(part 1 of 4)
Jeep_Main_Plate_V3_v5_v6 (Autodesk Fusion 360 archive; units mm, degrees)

design "Jeep_Main_Plate_V3_v5" references "Jeep_Left_Side_v8", "Jeep_Right_Side_v2"
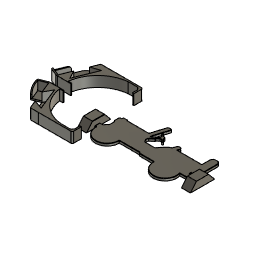
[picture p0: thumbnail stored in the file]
sketch "Sketch1" plane through (0, 0, 0) normal (0, 0, 1) x axis (1, 0, 0)
  line L1 (210, -40) -> (50, -40)
  line L2 (210, -120) -> (210, -40)
  line L3 (50, -120) -> (210, -120)
  line L4 (50, -40) -> (50, -120)
  point P2 (50, -40)
  point P3 (210, -40)
  point P5 (50, -120)
  horizontal L1
  vertical L2
  horizontal L3
  vertical L4
  dimension "d1" distance P2 P3 = 160
  dimension "d2" distance P2 P5 = 80
extrude "Extrude1" new body sketch "Sketch1" along normal blind 10.382
sketch "Sketch2" plane through (0, 0, 10.382) normal (0, 0, 1) x axis (-1, 0, 0)
  line L1 (-210, 120) -> (-50, 120)
  line L2 (-210, 40) -> (-210, 120)
  line L3 (-50, 40) -> (-210, 40)
  line L4 (-50, 120) -> (-50, 40)
  line L5 (-210, 120) -> (-50, 120)
  line L6 (-210, 118) -> (-210, 120)
  line L7 (-50, 118) -> (-210, 118)
  line L8 (-50, 120) -> (-50, 118)
  point P2 (-50, 120)
  point P6 (-50, 120)
  point P9 (-50, 118)
  horizontal L5
  vertical L6
  horizontal L7
  vertical L8
  coincident P2 P6
  dimension "d5" distance P6 P9 = 2
extrude "Extrude2" add sketch "Sketch2" profile of L1 L2 L4 L5 L6 L7 L8 along normal blind 11.697
sketch "Sketch3" plane through (50, 0, 0) normal (-1, 0, 0) x axis (0, -1, 0)
  line L1 (120, 0) -> (40, 0)
  line L2 (120, 22.079) -> (120, 0)
  line L3 (118, 22.079) -> (120, 22.079)
  line L4 (118, 10.382) -> (118, 22.079)
  line L5 (40, 10.382) -> (118, 10.382)
  line L6 (40, 0) -> (40, 10.382)
  line L7 (100.521, 10.382) -> (118, 10.382)
  line L8 (118, 0) -> (118, 10.382)
  line L9 (109.201, 0) -> (118, 0)
  line L10 (74.448, 0) -> (109.201, 0)
  line L11 (83.183, 10.382) -> (100.521, 10.382)
  line L12 (74.448, 0) -> (83.183, 10.382)
  line L13 (109.201, 0) -> (100.521, 10.382)
  point P6 (118, 10.382)
  point P8 (118, 10.382)
  point P10 (118, 0)
  point P9 (100.521, 10.382)
  point P11 (109.201, 0)
  point P12 (74.448, 0)
  point P13 (83.183, 10.382)
  coincident P6 P8
  coincident L1 P10
  dimension "d8" distance P8 P9 = 17.479
  dimension "d9" distance P10 P11 = 8.799
  dimension "d10" distance P11 P12 = 34.753
  dimension "d11" distance P9 P13 = 17.338
extrude "Extrude3" cut sketch "Sketch3" profile of L1 L2 L3 L4 L5 L6 L7 L8 L9 L12 L13 against normal blind 13
sketch "Sketch4" plane through (0, 0, 10.382) normal (0, 0, 1) x axis (-1, 0, 0)
  line L1 (-63, 83.183) -> (-63, 40)
  line L2 (-50, 83.183) -> (-63, 83.183)
  line L3 (-50, 100.521) -> (-50, 83.183)
  line L4 (-63, 100.521) -> (-50, 100.521)
  line L5 (-63, 118) -> (-63, 100.521)
  line L6 (-210, 118) -> (-63, 118)
  line L7 (-210, 40) -> (-210, 118)
  line L8 (-63, 40) -> (-210, 40)
  line L9 (-63, 66.387) -> (-63, 74.448)
  line L10 (-130, 91.852) -> (-50, 91.852)
  line L11 (-63, 120) -> (-210, 120)
  line L12 (-130, 80) -> (-130, 120)
  line L13 (-78.4111, 82) -> (-181.5889, 82)
  line L14 (-78.4111, 78) -> (-78.4111, 82)
  line L15 (-181.5889, 78) -> (-78.4111, 78)
  line L16 (-181.5889, 82) -> (-181.5889, 78)
  line L17 (-78.4111, 78) -> (-181.5889, 82)
  line L18 (-181.5889, 78) -> (-78.4111, 82)
  line L19 (-181.5889, 78.2155) -> (-176.0304, 78.2155)
  line L20 (-181.5889, 82) -> (-181.5889, 78.2155)
  line L21 (-176.0304, 82) -> (-181.5889, 82)
  line L22 (-176.0304, 78.2155) -> (-176.0304, 82)
  circle C1 centre (-130, 80) radius 33.45
  point P11 (-63, 74.448)
  point P12 (-63, 74.448)
  point P14 (-50, 91.852)
  point P18 (-130, 120)
  point P19 (-130, 80)
  point P20 (-130, 80)
  point P25 (-130, 80)
  point P26 (-176.0304, 78.2155)
  point P13 (-63, 66.387)
  point P15 (-130, 91.852)
  point P22 (-78.4111, 82)
  point P23 (-78.4111, 78)
  coincident P11 P12
  midpoint L3 P14
  coincident L11 P18
  coincident P19 P20
  perpendicular L13 L14
  parallel L13 L15
  parallel L14 L16
  horizontal L13
  coincident L17 P25
  coincident L18 P25
  coincident P20 P25
  horizontal L19
  vertical L20
  horizontal L21
  vertical L22
  coincident L18 P26
  dimension "d14" distance P12 P13 = 8.061
  dimension "d15" distance P14 P15 = 80
  dimension "d16" distance P18 P19 = 40
  dimension "d17" diameter C1 = 66.9
  dimension "d20" distance P22 P23 = 4
extrude "Extrude6" cut sketch "Sketch4" profile of L13 L16 L19 L20 L21 L22 against normal blind 19
extrude "Extrude5" cut sketch "Sketch4" profile of L10 L12 C1 L13 L15 L16 against normal blind 8
extrude "Extrude4" cut sketch "Sketch4" profile of L10 L12 C1 against normal blind 7.7
sketch "Sketch5" plane through (210, 0, 0) normal (1, 0, 0) x axis (0, 1, 0)
  line L1 (-40, 0) -> (-120, 0)
  line L2 (-40, 10.382) -> (-40, 0)
  line L3 (-118, 10.382) -> (-40, 10.382)
  line L4 (-118, 22.079) -> (-118, 10.382)
  line L5 (-120, 22.079) -> (-118, 22.079)
  line L6 (-120, 10.382) -> (-120, 22.079)
  line L7 (-120, 0) -> (-120, 10.382)
  line L8 (-100.521, 10.382) -> (-109.201, 0)
  line L9 (-74.448, 0) -> (-83.183, 10.382)
  point P9 (-109.201, 0)
  point P11 (-109.201, 0)
  point P10 (-100.521, 10.382)
  point P12 (-100.521, 10.382)
  point P13 (-83.183, 10.382)
  point P15 (-83.183, 10.382)
  point P14 (-74.448, 0)
  point P16 (-74.448, 0)
  coincident P9 P11
  coincident P10 P12
  coincident P13 P15
  coincident P14 P16
extrude "Extrude7" cut sketch "Sketch5" against normal blind 13
sketch "Sketch6" plane through (0, 0, 10.382) normal (0, 0, 1) x axis (-1, 0, 0)
  line L1 (-197, 100.521) -> (-197, 118)
  line L2 (-210, 100.521) -> (-197, 100.521)
  line L3 (-210, 83.183) -> (-210, 100.521)
  line L4 (-197, 83.183) -> (-210, 83.183)
  line L5 (-197, 40) -> (-197, 83.183)
  line L6 (-63, 40) -> (-197, 40)
  line L7 (-63, 83.183) -> (-63, 40)
  line L8 (-50, 83.183) -> (-63, 83.183)
  line L9 (-50, 100.521) -> (-50, 83.183)
  line L10 (-63, 100.521) -> (-50, 100.521)
  line L11 (-63, 118) -> (-63, 100.521)
  line L12 (-197, 118) -> (-63, 118)
  line L13 (-181.5889, 78) -> (-163.3902, 78)
  line L14 (-181.5889, 82) -> (-181.5889, 78)
  line L15 (-163.3902, 82) -> (-181.5889, 82)
  line L16 (-63, 66.387) -> (-63, 74.448)
  line L17 (-197, 66.387) -> (-197, 74.448)
  arc A1 centre (-56.3945, 2.5515) radius 64.1763 clockwise from (-108.5118, 40) to (-63, 66.387)
  arc A2 centre (-337.6055, 2.5515) radius 64.1763 clockwise from (-331, 66.387) to (-285.4882, 40)
  arc A3 centre (-203.6081, 2.6588) radius 64.1763 clockwise from (-197.0026, 66.4943) to (-151.4908, 40.1073)
  arc A4 centre (-203.6081, 2.6588) radius 64.1763 clockwise from (-197.0026, 66.4943) to (-151.4908, 40.1073)
  arc A5 centre (-130, 80) radius 33.45 clockwise from (-163.3902, 82) to (-163.3902, 78)
  point P18 (-63, 74.448)
  point P19 (-63, 74.448)
  point P21 (-108.5118, 40)
  point P23 (-197, 74.448)
  point P24 (-197, 74.448)
  point P20 (-63, 66.387)
  point P27 (-331, 66.387)
  point P28 (-285.4882, 40)
  point P25 (-197, 66.387)
  coincident P18 P19
  coincident L6 P21
  coincident P23 P24
  symmetric L5 P20 P27
  symmetric L5 P21 P28
  symmetric L5 A1 A2
  dimension "d28" distance P19 P20 = 8.061
  dimension "d29" distance P24 P25 = 8.061
fillet "Fillet2" radius 50
fillet "Fillet3" radius 50
sketch "Sketch7" plane through (0, 0, 22.079) normal (0, 0, 1) x axis (-1, 0, 0)
  line L1 (-197, 118) -> (-197, 120)
  line L2 (-63, 118) -> (-197, 118)
  line L3 (-63, 120) -> (-63, 118)
  line L4 (-197, 120) -> (-63, 120)
  line L5 (-50, 100.521) -> (-50, 109.201)
  line L6 (-50, 74.448) -> (-50, 109.201)
  line L7 (-50, 109.201) -> (-63, 109.201)
  line L8 (-50, 124) -> (-50, 107.6507)
  line L9 (-71, 120) -> (-50, 120)
  line L10 (-106, 120) -> (-71, 120)
  line L11 (-71, 120) -> (-106, 120)
  line L12 (-71, 118) -> (-71, 120)
  line L13 (-106, 118) -> (-71, 118)
  line L14 (-106, 120) -> (-106, 118)
  point P10 (-50, 107.6507)
  point P12 (-50, 120)
  point P16 (-71, 118)
  point P13 (-71, 120)
  point P14 (-106, 120)
  coincident L5 P10
  perpendicular L7 L8
  coincident L8 P12
  horizontal L11
  vertical L12
  horizontal L13
  vertical L14
  coincident L2 P16
  dimension "d32" distance P12 P13 = 21
  dimension "d33" distance P13 P14 = 35
extrude "Extrude8" cut sketch "Sketch7" profile of L2 L4 L10 L11 L12 L13 L14 against normal blind 12
fillet "Fillet4" radius 2
fillet "Fillet5" radius 2
sketch "Sketch8" plane through (0, 0, 10.382) normal (0, 0, 1) x axis (-1, 0, 0)
  line L1 (-181.5889, 78) -> (-163.3902, 78)
  line L2 (-181.5889, 82) -> (-181.5889, 78)
  line L3 (-163.3902, 82) -> (-181.5889, 82)
  curve K1 (-197, 83.183) -> (-147.2728, 40)
  line L4 (-112.7272, 40) -> (-147.2728, 40)
  curve K2 (-112.7272, 40) -> (-63, 83.183)
  line L5 (-50, 83.183) -> (-63, 83.183)
  line L6 (-50, 100.521) -> (-50, 83.183)
  line L7 (-63, 100.521) -> (-50, 100.521)
  line L8 (-63, 118) -> (-63, 100.521)
  line L9 (-71, 118) -> (-63, 118)
  line L10 (-106, 118) -> (-71, 118)
  line L11 (-197, 118) -> (-106, 118)
  line L12 (-197, 100.521) -> (-197, 118)
  line L13 (-210, 100.521) -> (-197, 100.521)
  line L14 (-210, 83.183) -> (-210, 100.521)
  line L15 (-197, 83.183) -> (-210, 83.183)
  arc A1 centre (-130, 80) radius 33.45 clockwise from (-163.3902, 82) to (-163.3902, 78)
extrude "Extrude9" add of existing geometry blind 0.3
extrude "Extrude10" add of existing geometry blind 0.003
sketch "Sketch9" plane through (0, -120, 0) normal (0, -1, 0) x axis (1, 0, 0)
  line L1 (106, 10.382) -> (106, 20.079)
  line L2 (71, 10.382) -> (106, 10.382)
  line L3 (71, 20.079) -> (71, 10.382)
  line L4 (63, 22.079) -> (69, 22.079)
  line L5 (63, 0) -> (63, 22.079)
  line L6 (197, 0) -> (63, 0)
  line L7 (197, 22.079) -> (197, 0)
  line L8 (108, 22.079) -> (197, 22.079)
  line L9 (189, 10.382) -> (197, 10.382)
  line L10 (189, 22.079) -> (189, 10.382)
  line L11 (106, 10.382) -> (189, 10.382)
  arc A1 centre (108, 20.079) radius 2 clockwise from (106, 20.079) to (108, 22.079)
  arc A2 centre (69, 20.079) radius 2 clockwise from (69, 22.079) to (71, 20.079)
  point P14 (197, 10.382)
  point P15 (197, 10.382)
  point P17 (189, 22.079)
  point P5 (106, 10.382)
  point P18 (106, 10.382)
  point P16 (189, 10.382)
  coincident P14 P15
  coincident L8 P17
  vertical L10
  coincident P5 P18
  perpendicular L1 L11
  dimension "d42" distance P15 P16 = 8
extrude "Extrude11" cut sketch "Sketch9" profile of A1 L1 L8 L10 L11 against normal blind 8
sketch "Sketch10" plane through (0, 0, 10.382) normal (0, 0, 1) x axis (-1, 0, 0)
  line L1 (-181.5889, 78) -> (-163.3902, 78)
  line L2 (-181.5889, 82) -> (-181.5889, 78)
  line L3 (-163.3902, 82) -> (-181.5889, 82)
  line L4 (-197, 118) -> (-189, 118)
  line L5 (-197, 100.521) -> (-197, 118)
  line L6 (-210, 100.521) -> (-197, 100.521)
  line L7 (-210, 83.183) -> (-210, 100.521)
  line L8 (-197, 83.183) -> (-210, 83.183)
  curve K1 (-197, 83.183) -> (-147.2728, 40)
  line L9 (-112.7272, 40) -> (-147.2728, 40)
  curve K2 (-112.7272, 40) -> (-63, 83.183)
  line L10 (-50, 83.183) -> (-63, 83.183)
  line L11 (-50, 100.521) -> (-50, 83.183)
  line L12 (-63, 100.521) -> (-50, 100.521)
  line L13 (-63, 118) -> (-63, 100.521)
  line L14 (-71, 118) -> (-63, 118)
  line L15 (-71, 120) -> (-71, 118)
  line L16 (-189, 120) -> (-71, 120)
  line L17 (-189, 118) -> (-189, 120)
  line L18 (-168.0304, 76) -> (-184.0304, 76)
  line L19 (-168.0304, 84) -> (-168.0304, 76)
  line L20 (-184.0304, 84) -> (-168.0304, 84)
  line L21 (-184.0304, 76) -> (-184.0304, 84)
  line L22 (-168.0304, 84) -> (-184.0304, 76)
  line L23 (-184.0304, 84) -> (-168.0304, 76)
  line L24 (-176.0304, 82) -> (-176.0304, 78.2155)
  arc A1 centre (-130, 80) radius 33.45 clockwise from (-163.3902, 82) to (-163.3902, 78)
  point P26 (-176.0304, 80)
  point P24 (-168.0304, 84)
  point P25 (-184.0304, 84)
  point P23 (-168.0304, 76)
  perpendicular L18 L19
  parallel L18 L20
  parallel L19 L21
  horizontal L18
  coincident L22 P26
  coincident L23 P26
  coincident P26 L24
  dimension "d45" distance P24 P25 = 16
  dimension "d46" distance P23 P24 = 8
extrude "Extrude12" cut sketch "Sketch10" profile of L1 L2 L3 L18 L19 L20 L21 against normal blind 18
sketch "Sketch11" plane through (0, 0, 10.382) normal (0, 0, 1) x axis (-1, 0, 0)
  line L1 (-168.0304, 76) -> (-168.0304, 78)
  line L2 (-163.3902, 82) -> (-168.0304, 82)
  line L3 (-168.0304, 78) -> (-163.3902, 78)
  line L4 (-197, 118) -> (-189, 118)
  line L5 (-197, 100.521) -> (-197, 118)
  line L6 (-210, 100.521) -> (-197, 100.521)
  line L7 (-210, 83.183) -> (-210, 100.521)
  line L8 (-197, 83.183) -> (-210, 83.183)
  curve K1 (-197, 83.183) -> (-147.2728, 40)
  line L9 (-112.7272, 40) -> (-147.2728, 40)
  curve K2 (-112.7272, 40) -> (-63, 83.183)
  line L10 (-50, 83.183) -> (-63, 83.183)
  line L11 (-50, 100.521) -> (-50, 83.183)
  line L12 (-63, 100.521) -> (-50, 100.521)
  line L13 (-63, 118) -> (-63, 100.521)
  line L14 (-71, 118) -> (-63, 118)
  line L15 (-71, 120) -> (-71, 118)
  line L16 (-189, 120) -> (-71, 120)
  line L17 (-189, 118) -> (-189, 120)
  line L18 (-184.0304, 76) -> (-168.0304, 76)
  line L19 (-184.0304, 84) -> (-184.0304, 76)
  line L20 (-168.0304, 84) -> (-184.0304, 84)
  line L21 (-168.0304, 82) -> (-168.0304, 84)
  arc A1 centre (-130, 80) radius 33.45 clockwise from (-163.3902, 82) to (-163.3902, 78)
fillet "Fillet8" radius 2
extrude "Extrude13" add of existing geometry blind 8
delete_face "DeleteFace1"
sketch "Sketch12" plane through (0, 0, 0) normal (0, 0, -1) x axis (1, 0, 0)
  curve K1 (148.4368, 40) -> (197, 74.448)
  line L1 (210, 74.448) -> (197, 74.448)
  line L2 (210, 109.201) -> (210, 74.448)
  line L3 (197, 109.201) -> (210, 109.201)
  line L4 (197, 120) -> (197, 109.201)
  line L5 (63, 120) -> (197, 120)
  line L6 (63, 109.201) -> (63, 120)
  line L7 (50, 109.201) -> (63, 109.201)
  line L8 (50, 74.448) -> (50, 109.201)
  line L9 (63, 74.448) -> (50, 74.448)
  curve K2 (63, 74.448) -> (111.5632, 40)
  line L10 (148.4368, 40) -> (111.5632, 40)
  line L11 (130, 22.3394) -> (130, 120)
  point P16 (130, 120)
  midpoint L5 P16
  perpendicular L10 L11
canvas "Canvas1"
sketch "Sketch1" plane through (0, 0, 0) normal (0, 1, 0) x axis (1, 0, 0)
  curve K1 (10.5686, 5.4176) -> (7.4507, 12.2398)
  curve K2 (7.4678, 11.4993) -> (7.4336, 12.9803)
  curve K3 (7.8437, 8) -> (7.163, 10.6564)
  curve K4 (10.8595, 5.7408) -> (9.8417, 7.2843)
  curve K5 (10.9325, 5.256) -> (10.2047, 5.5792)
  line L1 (0.1507, 12.2398) -> (7.4507, 12.2398)
  line L2 (19.9623, 0.0202) -> (19.9623, 1.5392)
  line L3 (20.9623, 0.0202) -> (19.9623, 0.0202)
  line L4 (20.9623, 12.2398) -> (20.9623, 0.0202)
  line L5 (7.4507, 12.2398) -> (20.9623, 12.2398)
  line L6 (17.9374, 5.4176) -> (10.5686, 5.4176)
  line L7 (17.9374, 1.5392) -> (17.9374, 5.4176)
  line L8 (19.9623, 1.5392) -> (17.9374, 1.5392)
  point P2 (7.4507, 12.2398)
  point P3 (7.5033, 9.3282)
  point P4 (10.3506, 6.5125)
  point P5 (10.5686, 5.4176)
  point P14 (0.1507, 12.2398)
  point P16 (19.9623, 0.0202)
  point P17 (20.9623, 0.0202)
  midpoint P2 K2
  midpoint P3 K3
  midpoint P4 K4
  midpoint P5 K5
  vertical L2
  perpendicular L1 L4
  perpendicular L4 L5
  horizontal L6
  perpendicular L6 L7
  perpendicular L2 L8
  dimension "d1_1" distance P2 P14 = 7.3 (= "( 14.6 / 2 ) * 1 mm")
  dimension "d2_1" distance P16 P17 = 1
sketch "Sketch2" plane through (0, 0, 0) normal (0, 0, 1) x axis (1, 0, 0)
  circle C1 centre (0, 0) radius 7.3
  point P1 (0, 0)
  point P3 (0, 0)
  coincident P1 P3
  dimension "d3_1" diameter C1 = 14.6
sweep "Sweep1" sketch "Sketch1" TwistAngle 0 named "d8_1" TaperAngle 0 named "d9_1"
sketch "Sketch3" plane through (0, 0, -5.4176) normal (0, 0, 1) x axis (-1, 0, 0)
  line L1 (15.5088, -26.862) -> (7.4507, -12.905)
  line L2 (31.0176, 0) -> (0, 0)
  line L3 (0, -0.73) -> (0, 0)
  line L4 (0, -27.3973) -> (0, -0.73)
  line L5 (-15.5088, -26.862) -> (-7.4507, -12.905)
  line L6 (-15.5088, -26.862) -> (15.5088, -26.862)
  line L7 (7.4507, -12.905) -> (7.4507, 0)
  line L8 (7.4507, -30.9185) -> (7.4507, -26.862)
  line L9 (-7.4507, -12.905) -> (-7.4507, 0)
  line L10 (-7.4507, 0) -> (7.4507, 0)
  circle C1 centre (0, 0) radius 17.9374
  circle C2 centre (0, 0) radius 10.5686
  point P1 (0, 0)
  point P3 (0, 0)
  point P6 (0, 0)
  point P4 (15.5088, -26.862)
  point P9 (-15.5088, -26.862)
  point P10 (7.4507, 0)
  point P11 (7.4507, 0)
  point P13 (7.4507, -26.862)
  point P15 (-7.4507, 0)
  point P14 (7.4507, -12.905)
  point P16 (-7.4507, -12.905)
  point P17 (7.4507, 0)
  coincident P1 P3
  horizontal L2
  coincident P1 P6
  perpendicular L2 L3
  perpendicular L2 L4
  symmetric P4 L4 P9
  coincident P10 P11
  perpendicular L6 L7
  coincident L6 P13
  collinear L7 L8
  symmetric L4 P11 P15
  symmetric L4 P14 P16
  coincident P10 P17
  dimension "d10_1" angle L1 L2 = 60
extrude "Extrude1" cut sketch "Sketch3" profile of C1 C2 L1 L5 L6 L8 L9 L10 distance -24 named "d11_1"
sketch "Sketch4" plane through (0, 0, -5.4176) normal (0, 0, 1) x axis (-1, 0, 0)
  line L1 (-7.4507, -7.4955) -> (-7.4507, -12.905)
  line L2 (7.4507, -12.905) -> (7.4507, -7.4955)
  line L3 (8.9687, -15.5343) -> (7.4507, -12.905)
  line L4 (-7.4507, -12.905) -> (-8.9687, -15.5343)
  line L5 (10, 18.4233) -> (10, 20.9623)
  line L6 (10, 50.9623) -> (10, 20.9623)
  line L7 (0, 35.9623) -> (0, 20.9623)
  line L8 (0, 50.9623) -> (10, 50.9623)
  line L9 (-10, 50.9623) -> (-10, 20.9623)
  line L10 (0, 50.9623) -> (-10, 50.9623)
  line L11 (-10, 18.4233) -> (-10, 20.9623)
  arc A1 centre (0, 0) radius 10.5686 clockwise from (-7.4507, -7.4955) to (7.4507, -7.4955)
  arc A2 centre (0, 0) radius 17.9374 clockwise from (-8.9687, -15.5343) to (8.9687, -15.5343)
  arc A3 centre (0, 0) radius 20.9623 clockwise from (-10.4811, -18.1539) to (10.4811, -18.1539)
  arc A4 centre (0, 0) radius 19.9623 clockwise from (-9.9811, -17.2878) to (9.9811, -17.2878)
  point P12 (0, 20.9623)
  point P17 (10, 18.4233)
  point P13 (10, 20.9623)
  point P21 (-10, 20.9623)
  point P24 (-10, 18.4233)
  point P18 (10, 50.9623)
  point P22 (-10, 50.9623)
  point P20 (0, 50.9623)
  point P23 (0, 50.9623)
  midpoint A3 P12
  coincident A3 P17
  perpendicular L7 L8
  symmetric P13 L7 P21
  symmetric P17 L7 P24
  symmetric P18 L7 P22
  symmetric L7 P20 P23
  dimension "d13_1" distance P12 P13 = 10
extrude "Extrude2" add sketch "Sketch4" profile of A3 L5 L6 L8 L9 L10 L11 against normal blind 6.822 named "d15_1"
extrude "Extrude3" add of existing geometry blind 5.397 named "d17_1"
sketch "Sketch5" plane through (0, -50.9623, 0) normal (0, -1, 0) x axis (1, 0, 0)
  line L1 (-10, -12.2396) -> (-10, -0.0206)
  line L2 (10, -12.2396) -> (-10, -12.2396)
  line L3 (10, -0.0206) -> (10, -12.2396)
  line L4 (-10, -0.0206) -> (10, -0.0206)
  line L5 (10, -12.2396) -> (-10, -12.2396)
  line L6 (10, 7.7604) -> (10, -12.2396)
  line L7 (-10, 7.7604) -> (10, 7.7604)
  line L8 (-10, -12.2396) -> (-10, 7.7604)
  point P3 (-10, -12.2396)
  point P6 (-10, -12.2396)
  point P9 (-10, 7.7604)
  point P7 (10, -12.2396)
  horizontal L5
  vertical L6
  horizontal L7
  vertical L8
  coincident P3 P6
  dimension "d19_1" distance P6 P9 = 20
  dimension "d20_1" distance P6 P7 = 20
extrude "Extrude4" add sketch "Sketch5" profile of L4 L6 L7 L8 against normal blind 15 named "d21_1"
sketch "Sketch6" plane through (0, -50.9623, 0) normal (0, -1, 0) x axis (1, 0, 0)
  line L1 (-10, -12.2396) -> (-10, 7.7604)
  line L2 (10, -12.2396) -> (-10, -12.2396)
  line L3 (10, 7.7604) -> (10, -12.2396)
  line L4 (-10, 7.7604) -> (10, 7.7604)
  circle C1 centre (0, -2.2396) radius 6.35
  dimension "d23_1" diameter C1 = 12.7
extrude "Extrude6" cut of existing geometry blind -10 named "d26_1"
extrude "Extrude7" add of existing geometry blind 5 named "d28_1"
sketch "Sketch1" plane through (0, -40.9623, 0) normal (0, -1, 0) x axis (1, 0, 0)
  line L1 (-10, -12.2396) -> (-10, 7.7604)
  line L2 (10, -12.2396) -> (-10, -12.2396)
  line L3 (10, 7.7604) -> (10, -12.2396)
  line L4 (-10, 7.7604) -> (10, 7.7604)
extrude "Extrude8" cut of existing geometry blind -7.781 named "d31_1"
sketch "Sketch2" plane through (0, 0, 0) normal (1, 0, 0) x axis (0, 1, 0)
sketch "Sketch3" plane through (0, -40.9623, 0) normal (0, -1, 0) x axis (1, 0, 0)
  line L1 (-10, -0.0206) -> (10, -0.0206)
  line L2 (-10, -12.2396) -> (-10, -0.0206)
  line L3 (10, -12.2396) -> (-10, -12.2396)
  line L4 (10, -0.0206) -> (10, -12.2396)
  circle C1 centre (0, -6.1301) radius 3.175
  dimension "d33_1" diameter C1 = 6.35
extrude "Extrude9" cut sketch "Sketch3" profile of C1 against normal blind 9 named "d34_1"
thread "Thread2"
position "Position1"
sketch "Sketch13" plane through (0, 0, 0) normal (0, 0, -1) x axis (1, 0, 0)
  curve K1 (148.4368, 40) -> (197, 74.448)
  line L1 (210, 74.448) -> (197, 74.448)
  line L2 (210, 109.201) -> (210, 74.448)
  line L3 (197, 109.201) -> (210, 109.201)
  line L4 (197, 120) -> (197, 109.201)
  line L5 (63, 120) -> (197, 120)
  line L6 (63, 109.201) -> (63, 120)
  line L7 (50, 109.201) -> (63, 109.201)
  line L8 (50, 74.448) -> (50, 109.201)
  line L9 (63, 74.448) -> (50, 74.448)
  curve K2 (63, 74.448) -> (111.5632, 40)
  line L10 (148.4368, 40) -> (111.5632, 40)
  line L11 (130, 40) -> (130, 120)
  line L12 (143, 37.8497) -> (143, 79.9884)
  line L13 (120, 36.7317) -> (120, 79.9884)
  arc A1 centre (130, 77.0377) radius 7.4507 clockwise from (122.5493, 77.0377) to (137.4507, 77.0377)
  circle C1 centre (131.5, 79.9884) radius 11.5
  point P19 (130, 120)
  point P20 (130, 40)
  point P22 (143, 79.9884)
  point P24 (120, 79.9884)
  midpoint L5 P19
  midpoint L10 P20
  coincident C1 P22
  tangent C1 L12
  perpendicular L10 L12
  coincident C1 P24
  tangent C1 L13
  perpendicular L10 L13
  dimension "d54" diameter C1 = 23
extrude "Extrude15" cut sketch "Sketch13" profile of K1 L1 L2 L3 L4 L5 L10 L11 C1 L12 against normal blind 75
extrude "Extrude16" add of existing geometry blind 1.5 (= "( 3 / 2 ) * 1 mm")
mirror "Mirror1"
combine "Combine1"
extrude "Extrude14" cut sketch "Sketch13" profile of L10 L11 C1 L12 L13 against normal blind 85
work_plane "WorkPlane1"
fillet "Fillet12" radius 4
fillet "Fillet14" radius 1
canvas "Canvas1"
sketch "Sketch14" plane through (0, 0, 0) normal (0, 0, 1) x axis (1, 0, 0)
  line L1 (128.7982, -98.2647) -> (99.3211, -98.2647)
  line L2 (129.8583, -99.7804) -> (128.7982, -98.2647)
  line L3 (150.6139, -99.7804) -> (129.8583, -99.7804)
  line L4 (195.6291, -95.5573) -> (183.8668, -95.5573)
  line L5 (195.6291, -89.014) -> (195.6291, -95.5573)
  line L6 (191.3607, -89.014) -> (195.6291, -89.014)
  line L7 (191.3607, -86.7498) -> (191.3607, -89.014)
  line L8 (191.9972, -87.3863) -> (191.3607, -86.7498)
  line L9 (197.3484, -87.3863) -> (191.9972, -87.3863)
  line L10 (200.0535, -84.1624) -> (197.3484, -87.3863)
  line L11 (200.0535, -56.2188) -> (200.0535, -84.1624)
  line L12 (197.3038, -52.9418) -> (200.0535, -56.2188)
  line L13 (204.3313, -56.2188) -> (200.0535, -56.2188)
  line L14 (191.2909, -52.9418) -> (197.3038, -52.9418)
  line L15 (188.7254, -56.2188) -> (191.2909, -52.9418)
  line L16 (188.7254, -68.4969) -> (188.7254, -56.2188)
  line L17 (153.2654, -68.4969) -> (188.7254, -68.4969)
  line L18 (154.5138, -65.0671) -> (153.2654, -68.4969)
  line L19 (156.9154, -68.4969) -> (153.2654, -68.4969)
  line L20 (146.35, -69.1346) -> (148.3154, -63.7348)
  curve K1 (133.8463, -81.3637) -> (146.35, -69.1346)
  line L21 (119.9542, -81.3637) -> (133.8463, -81.3637)
  curve K2 (118.0954, -74.6133) -> (119.9542, -81.3637)
  line L22 (122.943, -70.3338) -> (118.0954, -74.6133)
  line L23 (122.943, -69.4437) -> (122.943, -70.3338)
  line L24 (125.8689, -66.8608) -> (122.943, -69.4437)
  line L25 (126.2719, -66.505) -> (125.8689, -66.8608)
  line L26 (128.6728, -66.505) -> (126.2719, -66.505)
  line L27 (133.5934, -68.6449) -> (132.1679, -70.0502)
  line L28 (129.626, -62.6847) -> (129.626, -64.6204)
  line L29 (128.1495, -61.187) -> (129.626, -62.6847)
  line L30 (126.2413, -61.187) -> (128.1495, -61.187)
  line L31 (121.316, -59.0423) -> (122.7416, -57.6369)
  line L32 (124.7107, -64.9095) -> (124.7107, -62.4858)
  line L33 (121.4619, -67.7775) -> (124.7107, -64.9095)
  line L34 (120.8815, -67.7775) -> (121.4619, -67.7775)
  line L35 (117.3916, -70.8584) -> (120.8815, -67.7775)
  line L36 (117.3916, -68.4195) -> (117.3916, -70.8584)
  line L37 (123.9443, -47.4165) -> (117.3916, -68.4195)
  line L38 (111.5923, -67.2973) -> (111.5923, -67.6502)
  line L39 (117.7949, -47.4165) -> (111.5923, -67.2973)
  line L40 (80.2795, -67.6502) -> (111.5923, -67.6502)
  line L41 (79.7805, -66.6096) -> (80.2795, -67.6502)
  line L42 (73.9859, -66.6096) -> (79.7805, -66.6096)
  line L43 (73.6272, -67.1299) -> (73.9859, -66.6096)
  line L44 (73.6272, -69.0102) -> (73.6272, -67.1299)
  line L45 (71.4131, -69.0102) -> (73.6272, -69.0102)
  line L46 (70.521, -70.3042) -> (71.4131, -69.0102)
  line L47 (70.521, -76.4816) -> (70.521, -70.3042)
  line L48 (71.964, -78.6852) -> (70.521, -76.4816)
  line L49 (71.964, -85.1569) -> (71.964, -78.6852)
  line L50 (63.3354, -90.1913) -> (67.5701, -90.1913)
  line L51 (63.3354, -97.3274) -> (63.3354, -90.1913)
  line L52 (65.3754, -97.3274) -> (63.3354, -97.3274)
  line L53 (129.626, -64.6204) -> (133.5934, -68.6449)
  line L54 (122.7416, -57.6369) -> (126.2413, -61.187)
  line L55 (124.7107, -62.4858) -> (121.316, -59.0423)
  line L56 (132.1679, -70.0502) -> (128.6728, -66.505)
  circle C1 centre (82.3251, -98.6346) radius 17
  circle C2 centre (167.5989, -100.4925) radius 17
  arc A1 centre (151.1259, -65.7443) radius 3.455 clockwise from (148.3154, -63.7348) to (154.5138, -65.0671)
  arc A2 centre (120.8696, -50.3705) radius 4.2638 clockwise from (117.7949, -47.4165) to (123.9443, -47.4165)
  point P4 (99.3211, -98.2647)
  point P7 (150.6139, -99.7804)
  point P8 (183.8668, -95.5573)
  point P65 (71.964, -85.1569)
  point P66 (67.5701, -90.1913)
  point P69 (65.3754, -97.3274)
  point P38 (128.6728, -66.505)
  point P70 (126.2413, -61.187)
  coincident C1 P4
  horizontal L1
  coincident C2 P7
  parallel L1 L3
  coincident C2 P8
  parallel L3 L4
  perpendicular L4 L5
  perpendicular L5 L6
  perpendicular L6 L7
  perpendicular L7 L9
  perpendicular L9 L11
  horizontal L13
  perpendicular L11 L14
  perpendicular L14 L16
  perpendicular L16 L17
  horizontal L19
  parallel L18 L20
  horizontal L21
  vertical L23
  parallel L22 L24
  parallel L24 L25
  perpendicular L23 L26
  perpendicular L27 L55
  perpendicular L27 L53
  vertical L28
  perpendicular L27 L29
  horizontal L30
  perpendicular L31 L55
  perpendicular L26 L32
  parallel L24 L33
  perpendicular L23 L34
  parallel L33 L35
  perpendicular L34 L36
  vertical L38
  parallel L37 L39
  perpendicular L38 L40
  parallel L40 L42
  perpendicular L42 L44
  perpendicular L44 L45
  parallel L43 L46
  perpendicular L45 L47
  coincident C1 P65
  parallel L47 L49
  coincident C1 P66
  perpendicular L49 L50
  perpendicular L50 L51
  coincident C1 P69
  perpendicular L51 L52
  coincident P38 L55
  coincident P70 L53
  collinear L53 L54
  collinear L55 L56
  dimension "d68" diameter C1 = 34
  dimension "d69" diameter C2 = 34
  dimension "d70" angle L7 L8 = 45
  dimension "d71" angle L9 L10 = 130
  dimension "d72" angle L12 L13 = 130
  dimension "d73" angle L18 L19 = 70
sketch "Sketch15" plane through (0, 0, 0) normal (0, 0, -1) x axis (1, 0, 0)
  line L1 (213, 74.448) -> (198.6339, 74.448)
  line L2 (213, 109.201) -> (213, 74.448)
  line L3 (200, 109.201) -> (213, 109.201)
  line L4 (200, 120) -> (200, 109.201)
  line L5 (63, 120) -> (200, 120)
  line L6 (63, 109.201) -> (63, 120)
  line L7 (50, 109.201) -> (63, 109.201)
  line L8 (50, 74.448) -> (50, 109.201)
  line L9 (64.3661, 74.448) -> (50, 74.448)
  curve K1 (64.3661, 74.448) -> (111.7164, 41)
  line L10 (119, 41) -> (111.7164, 41)
  line L11 (119, 79.9884) -> (119, 41)
  line L12 (144, 41) -> (144, 79.9884)
  line L13 (151.2836, 41) -> (144, 41)
  curve K2 (151.2836, 41) -> (198.6339, 74.448)
  line L14 (200, 120) -> (63, 120)
  line L15 (200, 36.1577) -> (200, 120)
  line L16 (63, 36.1577) -> (200, 36.1577)
  line L17 (63, 120) -> (63, 36.1577)
  arc A1 centre (131.5, 79.9884) radius 12.5 clockwise from (119, 79.9884) to (144, 79.9884)
  point P7 (63, 120)
  point P19 (63, 120)
  horizontal L14
  vertical L15
  horizontal L16
  vertical L17
  coincident P7 P19
extrude "Extrude17" cut sketch "Sketch15" profile of L1 L4 L5 L6 L9 K1 L10 L11 A1 L12 L13 K2 L14 L15 L16 L17 against normal blind 75
extrude "Extrude18" new body sketch "Sketch14" profile of C1 C2 L1 L2 L3 L4 L5 L6 L7 L8 L9 L10 L11 L12 L14 L15 L16 L17 L18 L20 A1 K1 L21 K2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 along normal blind 3.4 (= "10 mm - 6.6 mm")
fillet "Fillet15" radius 0.4
extrude "Extrude19" add of existing geometry blind 4.371
extrude "Extrude20" add of existing geometry blind 1
fillet "Fillet16" radius 0.4
fillet "Fillet17" radius 0.4
component_insert "Component Insert1"
component_insert "Component Insert2"
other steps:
create_component "CreateComponent1"
create_component "CreateComponent1"

design "Jeep_Left_Side_v8"
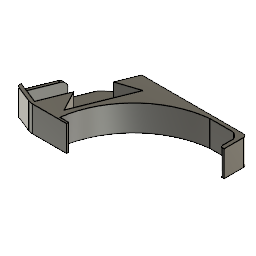
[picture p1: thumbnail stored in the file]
sketch "Sketch1" plane through (0, 0, 0) normal (0, 0, 1) x axis (1, 0, 0)
  line L1 (56, 0) -> (0, 0)
  line L2 (0, 1.2) -> (56, 1.2)
  line L3 (0, 0) -> (0, 1.2)
  line L4 (-1.2, 1.2) -> (0, 1.2)
  line L5 (-1.2, -43.8) -> (-1.2, 1.2)
  line L6 (0, -43.8) -> (-1.2, -43.8)
  line L7 (0, 1.2) -> (0, -43.8)
  line L8 (5, -43.8) -> (0, -43.8)
  line L9 (5, -42.6) -> (5, -43.8)
  line L10 (0, -42.6) -> (5, -42.6)
  line L11 (0, -43.8) -> (0, -42.6)
  line L12 (54.8, 0) -> (56, 0)
  line L13 (61, 1.2) -> (56, 1.2)
  line L14 (56, 0) -> (61, 0)
  line L15 (59.8, 0) -> (61, 0)
  line L16 (62, 1.2) -> (61, 1.2)
  line L17 (62, 0) -> (62, 1.2)
  line L18 (61, 0) -> (62, 0)
  line L19 (60.8, 0) -> (62, 0)
  line L20 (40.8, 0) -> (60.8, 0)
  line L21 (14.1421, -14.1421) -> (0, 0)
  line L22 (43.8, 0) -> (60.8, 0)
  line L23 (60.8, 0) -> (62, 0)
  line L24 (60.8, -13) -> (60.8, 0)
  line L25 (62, -13) -> (60.8, -13)
  line L26 (62, 0) -> (62, -13)
  line L27 (58.8, 0) -> (60.8, 0)
  line L28 (60.8, -2) -> (60.8, 0)
  line L29 (59.3858, -1.4142) -> (60.8, 0)
  line L30 (62.8, 0) -> (60.8, 0)
  line L31 (57.3, 0) -> (60.8, 0)
  line L32 (60.8, -3.5) -> (60.8, 0)
  line L33 (57.3, 0) -> (60.8, 0)
  line L34 (62, -11) -> (62, -13)
  line L35 (60.8, -11) -> (62, -11)
  arc A1 centre (49.0833, -49.2491) radius 49.5316 clockwise from (0, -42.6) to (43.8, 0)
  arc A2 centre (49.0833, -49.2491) radius 50.7316 clockwise from (-1.1891, -42.4389) to (43.672, 1.1932)
  arc A3 centre (54.6577, -6.1423) radius 6.6865 clockwise from (57.3, 0) to (60.8, -3.5)
  point P1 (0, 0)
  point P2 (0, 0)
  point P22 (0, 0)
  point P23 (14.1421, -14.1421)
  point P33 (60.8, -2)
  point P36 (57.3, 0)
  point P34 (59.3858, -1.4142)
  point P41 (60.8, -11)
  point P5 (0, 1.2)
  point P6 (-1.2, 1.2)
  point P8 (0, -43.8)
  point P9 (5, -43.8)
  point P11 (0, -42.6)
  point P13 (61, 1.2)
  point P17 (62, 1.2)
  point P20 (60.8, 0)
  point P24 (43.8, 0)
  point P18 (62, 0)
  point P31 (62, -13)
  point P29 (60.8, 0)
  point P37 (60.8, -3.5)
  point P38 (57.3, 0)
  point P40 (62, -11)
  horizontal L1
  horizontal L2
  vertical L3
  coincident P1 P2
  horizontal L4
  vertical L5
  horizontal L6
  vertical L7
  horizontal L8
  vertical L9
  horizontal L10
  vertical L11
  horizontal L12
  horizontal L13
  horizontal L14
  horizontal L15
  horizontal L16
  vertical L17
  horizontal L18
  horizontal L19
  coincident P1 P22
  coincident P23 A1
  horizontal L23
  vertical L24
  horizontal L25
  vertical L26
  coincident L24 P33
  perpendicular L18 L28
  horizontal L30
  coincident L14 P36
  coincident L22 P36
  coincident L20 P36
  coincident P34 A3
  coincident L24 P41
  perpendicular L24 L35
  dimension "d26" distance P2 P5 = 1.2
  dimension "d27" distance P5 P6 = 1.2
  dimension "d28" distance P5 P8 = 45
  dimension "d29" distance P8 P9 = 5
  dimension "d30" distance P8 P11 = 1.2
  dimension "d34" distance P13 P17 = 1
  dimension "d38" distance P22 P23 = 20
  dimension "d39" distance P20 P24 = 17
  dimension "d40" = 1.2
  dimension "d41" distance P18 P31 = 13
  dimension "d42" distance P18 P29 = 1.2
  dimension "d45" angle L29 L30 = 135
  dimension "d46" distance P29 P34 = 2
  dimension "d47" distance P20 P37 = 3.5
  dimension "d48" distance P29 P38 = 3.5
  dimension "d49" distance P31 P40 = 2
extrude "Extrude1" new body sketch "Sketch1" profile of L1 L2 L3 L4 L5 L6 L7 L8 L9 L10 L11 L12 L13 L14 L15 L16 L17 L18 L19 L20 L21 L22 A1 A2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 along normal blind 5
sketch "Sketch2" plane through (0, 0, 0) normal (0, 0, 1) x axis (1, 0, 0)
  line L1 (5, -43.8) -> (-1.2, -43.8)
  line L2 (36.9084, 0) -> (0, 0)
  line L3 (-3.5615, -43.8) -> (14.2717, 0)
  line L4 (-4.6753, -43.3534) -> (-3.5615, -43.8)
  line L5 (12.7071, 0) -> (-4.6753, -43.3534)
  line L6 (-1.2, -43.8) -> (-3.5615, -43.8)
  line L7 (-9.9836, -40.5566) -> (-4.6753, -43.3534)
  line L8 (-5.7884, -32.5942) -> (-9.9836, -40.5566)
  line L9 (-1.3079, -34.9548) -> (-5.7884, -32.5942)
  line L10 (9.3578, -8.3536) -> (12.7071, 0)
  line L11 (3.7888, -6.1207) -> (9.3578, -8.3536)
  line L12 (6.2428, 0) -> (3.7888, -6.1207)
  line L13 (-1.2, -38) -> (-1.2, -43.8)
  line L14 (-3.5615, -43.8) -> (-1.2, -38)
  point P7 (14.2717, 0)
  point P10 (12.7071, 0)
  point P3 (-1.2, -43.8)
  point P11 (-1.2, -43.8)
  point P14 (-1.3079, -34.9548)
  point P17 (6.2428, 0)
  point P18 (-1.2, -38)
  point P8 (-3.5615, -43.8)
  point P9 (-4.6753, -43.3534)
  point P12 (-9.9836, -40.5566)
  point P13 (-5.7884, -32.5942)
  point P15 (9.3578, -8.3536)
  point P16 (3.7888, -6.1207)
  coincident L2 P7
  coincident L2 P10
  perpendicular L4 L5
  coincident P3 P11
  parallel L1 L6
  coincident L5 P14
  perpendicular L8 L9
  coincident L2 P17
  perpendicular L11 L12
  coincident L3 P18
  perpendicular L1 L13
  dimension "d52" distance P8 P9 = 1.2
  dimension "d55" distance P9 P12 = 6
  dimension "d56" distance P12 P13 = 9
  dimension "d57" distance P10 P15 = 9
  dimension "d58" distance P15 P16 = 6
extrude "Extrude2" add sketch "Sketch2" profile of L2 L3 L4 L5 L6 L7 L8 L9 L10 L11 L12 L13 L14 along normal blind 15
extrude "Extrude3" add of existing geometry blind 10
sketch "Sketch3" plane through (0, 0, 15) normal (0, 0, 1) x axis (-1, 0, 0)
  line L1 (-14.2717, 0) -> (0, 35.0527)
  line L2 (-36.9084, 0) -> (-14.2717, 0)
  line L3 (0, 35.0527) -> (0, 36.4223)
  line L4 (-3.7888, 6.1207) -> (-6.2428, 0)
  line L5 (-9.3578, 8.3536) -> (-3.7888, 6.1207)
  line L6 (0, 31.6928) -> (-9.3578, 8.3536)
  line L7 (0, 0) -> (0, 31.6928)
  line L8 (-6.2428, 0) -> (0, 0)
  line L9 (-5, 43.8) -> (3.5615, 43.8)
  line L10 (-5, 42.6) -> (-5, 43.8)
  line L11 (0, 42.6) -> (-5, 42.6)
  line L12 (-57.3, 0) -> (-43.8, 0)
  line L13 (-60.8, 11) -> (-60.8, 3.5)
  line L14 (-62, 11) -> (-60.8, 11)
  line L15 (-62, -1.2) -> (-62, 11)
  line L16 (1.2, -1.2) -> (-62, -1.2)
  line L17 (1.2, 34.6857) -> (1.2, -1.2)
  line L18 (1.3079, 34.9548) -> (1.2, 34.6857)
  line L19 (5.7884, 32.5942) -> (1.3079, 34.9548)
  line L20 (9.9836, 40.5566) -> (5.7884, 32.5942)
  line L21 (4.6753, 43.3534) -> (9.9836, 40.5566)
  line L22 (3.5615, 43.8) -> (4.6753, 43.3534)
  line L23 (1.2, 34.6857) -> (0, 31.6928)
  line L24 (-7.3301, -2.7117) -> (-5.8415, 1.001)
  arc A1 centre (-49.0833, 49.2491) radius 50.7316 clockwise from (0, 36.4223) to (-36.9084, 0)
  arc A2 centre (-49.0833, 49.2491) radius 49.5316 clockwise from (0, 42.6) to (-43.8, 0)
  arc A3 centre (-54.6577, 6.1423) radius 6.6865 clockwise from (-57.3, 0) to (-60.8, 3.5)
  point P10 (0, 31.6928)
  point P29 (0, 31.6928)
  point P24 (1.2, 34.6857)
  point P30 (1.2, 34.6857)
  point P31 (-5.8415, 1.001)
  point P32 (-7.3301, -2.7117)
  coincident P10 P29
  coincident P24 P30
  coincident L4 P31
  dimension "d63" distance P31 P32 = 4
extrude "Extrude4" cut sketch "Sketch3" profile of L7 L8 L16 L17 L23 L24 against normal blind 19
sketch "Sketch4" plane through (0, 0, 0) normal (0, 0, 1) x axis (1, 0, 0)
sketch "Sketch5" plane through (0, 0, 0) normal (0, 0, 1) x axis (1, 0, 0)
  line L1 (36.9084, 0) -> (14.2717, 0)
  line L2 (36.9084, 0) -> (14.2717, 0)
  line L3 (0, -35.0527) -> (14.2717, 0)
  line L4 (0, -36.4223) -> (0, -35.0527)
  arc A1 centre (49.0833, -49.2491) radius 50.7316 clockwise from (0, -36.4223) to (36.9084, 0)
  arc A2 centre (49.0833, -49.2491) radius 50.7316 clockwise from (0, -36.4223) to (36.9084, 0)
  point P2 (14.2717, 0)
  point P6 (14.2717, 0)
  point P3 (36.9084, 0)
  point P7 (36.9084, 0)
  point P9 (36.9084, 0)
  point P8 (0, -36.4223)
  point P11 (0, -36.4223)
  point P14 (0, -35.0527)
  point P15 (0, -35.0527)
  point P12 (0, -36.4223)
  point P16 (0, -36.4223)
  coincident P2 P6
  coincident P3 P7
  coincident P3 P9
  coincident P8 P11
  coincident P14 P15
  coincident P12 P16
extrude "Extrude5" add sketch "Sketch5" along normal blind 15
sketch "Sketch6" plane through (0, 0, 0) normal (0, 0, 1) x axis (1, 0, 0)
extrude "Extrude6" add of existing geometry blind 1
fillet "Fillet1" radius 2.5
fillet "Fillet2" radius 3
sketch "Sketch7" plane through (0, 0, 15) normal (0, 0, 1) x axis (-1, 0, 0)
  line L1 (-8.724, -2.2) -> (-59, -2.2)
  line L2 (-3.7888, 6.1207) -> (-6.724, -1.2)
  line L3 (-9.3578, 8.3536) -> (-3.7888, 6.1207)
  line L4 (1.3079, 34.9548) -> (-9.3578, 8.3536)
  line L5 (5.7884, 32.5942) -> (1.3079, 34.9548)
  line L6 (9.9836, 40.5566) -> (5.7884, 32.5942)
  line L7 (4.6753, 43.3534) -> (9.9836, 40.5566)
  line L8 (3.5615, 43.8) -> (4.6753, 43.3534)
  line L9 (-5, 43.8) -> (3.5615, 43.8)
  line L10 (-5, 42.6) -> (-5, 43.8)
  line L11 (0, 42.6) -> (-5, 42.6)
  line L12 (-57.3, 0) -> (-43.8, 0)
  line L13 (-60.8, 11) -> (-60.8, 3.5)
  line L14 (-62, 11) -> (-60.8, 11)
  line L15 (-62, 0.8) -> (-62, 11)
  line L16 (-15.2943, -6.4527) -> (-7.555, 12.8499)
  line L17 (6.3033, 47.414) -> (-1.0507, 29.0723)
  arc A1 centre (-59, 0.8) radius 3 clockwise from (-59, -2.2) to (-62, 0.8)
  arc A2 centre (-8.724, 0.3) radius 2.5 clockwise from (-6.724, -1.2) to (-8.724, -2.2)
  arc A3 centre (-49.0833, 49.2491) radius 49.5316 clockwise from (0, 42.6) to (-43.8, 0)
  arc A4 centre (-54.6577, 6.1423) radius 6.6865 clockwise from (-57.3, 0) to (-60.8, 3.5)
  point P25 (-7.555, 12.8499)
  point P27 (-1.0507, 29.0723)
  coincident L4 P25
  parallel L4 L16
  coincident L4 P27
  parallel L4 L17
extrude "Extrude7" cut sketch "Sketch7" profile of L1 A2 L2 L3 L5 L6 L7 L16 L17 against normal blind 55
sketch "Sketch8" plane through (0, 0, 15) normal (0, 0, 1) x axis (-1, 0, 0)
  line L1 (4.6753, 43.3534) -> (-13.5892, -2.2)
  line L2 (3.5615, 43.8) -> (4.6753, 43.3534)
  line L3 (-5, 43.8) -> (3.5615, 43.8)
  line L4 (-5, 42.6) -> (-5, 43.8)
  line L5 (0, 42.6) -> (-5, 42.6)
  line L6 (-57.3, 0) -> (-43.8, 0)
  line L7 (-60.8, 11) -> (-60.8, 3.5)
  line L8 (-62, 11) -> (-60.8, 11)
  line L9 (-62, 0.8) -> (-62, 11)
  line L10 (-13.5892, -2.2) -> (-59, -2.2)
  line L11 (9.3161, 41.4927) -> (4.6753, 43.3534)
  line L12 (6.339, 34.0673) -> (9.3161, 41.4927)
  line L13 (1.9508, 38.1593) -> (6.339, 34.0673)
  line L14 (12.339, 34.0673) -> (6.339, 34.0673)
  line L15 (-9.142, -4.5438) -> (7.8275, 37.78)
  line L16 (-8.2023, -2.2) -> (-13.5892, -2.2)
  line L17 (-5.2251, 5.2254) -> (-8.2023, -2.2)
  line L18 (-12.6359, 5.303) -> (-5.2251, 5.2254)
  line L19 (2.1861, 5.2254) -> (-5.2251, 5.2254)
  line L20 (13, 43.8) -> (3.5615, 43.8)
  line L21 (11.1769, 46.1335) -> (9.3161, 41.4927)
  arc A1 centre (-49.0833, 49.2491) radius 49.5316 clockwise from (0, 42.6) to (-43.8, 0)
  arc A2 centre (-54.6577, 6.1423) radius 6.6865 clockwise from (-57.3, 0) to (-60.8, 3.5)
  arc A3 centre (-59, 0.8) radius 3 clockwise from (-59, -2.2) to (-62, 0.8)
  point P3 (4.6753, 43.3534)
  point P18 (4.6753, 43.3534)
  point P23 (7.8275, 37.78)
  point P2 (-13.5892, -2.2)
  point P25 (-13.5892, -2.2)
  point P26 (-8.2023, -2.2)
  point P4 (3.5615, 43.8)
  point P30 (3.5615, 43.8)
  point P19 (9.3161, 41.4927)
  point P20 (6.339, 34.0673)
  point P21 (1.9508, 38.1593)
  point P27 (-5.2251, 5.2254)
  point P32 (11.1769, 46.1335)
  coincident P3 P18
  horizontal L14
  midpoint L12 P23
  parallel L12 L15
  coincident P2 P25
  coincident L15 P26
  parallel L10 L16
  horizontal L19
  coincident P4 P30
  parallel L3 L20
  dimension "d75" distance P18 P19 = 5
  dimension "d76" distance P19 P20 = 8
  dimension "d77" angle L13 L14 = 137
  dimension "d78" distance P20 P21 = 6
  dimension "d79" distance P26 P27 = 8
  dimension "d80" angle L18 L19 = 179.4
  dimension "d81" distance P19 P32 = 5
extrude "Extrude8" add sketch "Sketch8" profile of L1 L2 L11 L12 L13 L15 L16 L17 L18 L20 L21 against normal blind 15
sketch "Sketch9" plane through (0, 0, 15) normal (0, 0, 1) x axis (-1, 0, 0)
  line L1 (2.418, 37.7236) -> (-10.5895, 5.2816)
  line L2 (6.339, 34.0673) -> (2.418, 37.7236)
  line L3 (10.2413, 43.8) -> (6.339, 34.0673)
  line L4 (-5, 43.8) -> (10.2413, 43.8)
  line L5 (-5, 42.6) -> (-5, 43.8)
  line L6 (0, 42.6) -> (-5, 42.6)
  line L7 (-57.3, 0) -> (-43.8, 0)
  line L8 (-60.8, 11) -> (-60.8, 3.5)
  line L9 (-62, 11) -> (-60.8, 11)
  line L10 (-62, 0.8) -> (-62, 11)
  line L11 (-8.2023, -2.2) -> (-59, -2.2)
  line L12 (-5.2251, 5.2254) -> (-8.2023, -2.2)
  line L13 (-10.5895, 5.2816) -> (-5.2251, 5.2254)
  line L14 (-5.9624, 11.4479) -> (-7.8187, 12.1922)
  line L15 (-11.4084, -2.1682) -> (-5.9624, 11.4479)
  line L16 (8.7025, 11.4479) -> (-5.9624, 11.4479)
  line L17 (8.6956, 47.9984) -> (-7.264, 8.1935)
  line L18 (-11.5321, -2.4773) -> (-11.3387, -1.9939)
  arc A1 centre (-49.0833, 49.2491) radius 49.5316 clockwise from (0, 42.6) to (-43.8, 0)
  arc A2 centre (-54.6577, 6.1423) radius 6.6865 clockwise from (-57.3, 0) to (-60.8, 3.5)
  arc A3 centre (-59, 0.8) radius 3 clockwise from (-59, -2.2) to (-62, 0.8)
  point P21 (-7.8187, 12.1922)
  point P25 (-7.264, 8.1935)
  point P27 (-11.3387, -1.9939)
  point P22 (-5.9624, 11.4479)
  coincident L1 P21
  horizontal L16
  coincident L15 P25
  parallel L1 L17
  coincident L15 P27
  parallel L15 L18
  dimension "d84" distance P21 P22 = 2
  dimension "d85" angle L15 L16 = 111.8
extrude "Extrude9" cut sketch "Sketch9" profile of L2 L3 L4 L11 L12 L13 L15 L17 L18 against normal blind 20
sketch "Sketch10" plane through (0, 0, 15) normal (0, 0, 1) x axis (-1, 0, 0)
  line L1 (-8.4377, 5.259) -> (-11.4211, -2.2)
  line L2 (-10.5895, 5.2816) -> (-8.4377, 5.259)
  line L3 (2.418, 37.7236) -> (-10.5895, 5.2816)
  line L4 (3.9887, 36.2589) -> (2.418, 37.7236)
  line L5 (7.0123, 43.8) -> (3.9887, 36.2589)
  line L6 (-5, 43.8) -> (7.0123, 43.8)
  line L7 (-5, 42.6) -> (-5, 43.8)
  line L8 (0, 42.6) -> (-5, 42.6)
  line L9 (-57.3, 0) -> (-43.8, 0)
  line L10 (-60.8, 11) -> (-60.8, 3.5)
  line L11 (-62, 11) -> (-60.8, 11)
  line L12 (-62, 0.8) -> (-62, 11)
  line L13 (-11.4211, -2.2) -> (-59, -2.2)
  line L14 (7.1686, 14.1022) -> (-5.0833, 19.0145)
  line L15 (25.776, 60.5109) -> (7.1686, 14.1022)
  line L16 (-11.4388, -32.3065) -> (7.1686, 14.1022)
  line L17 (9, -2.2) -> (-11.4211, -2.2)
  line L18 (57.0123, 43.8) -> (7.0123, 43.8)
  line L19 (34.8575, 32.6356) -> (7.0123, 43.8)
  arc A1 centre (-49.0833, 49.2491) radius 49.5316 clockwise from (0, 42.6) to (-43.8, 0)
  arc A2 centre (-54.6577, 6.1423) radius 6.6865 clockwise from (-57.3, 0) to (-60.8, 3.5)
  arc A3 centre (-59, 0.8) radius 3 clockwise from (-59, -2.2) to (-62, 0.8)
  point P21 (-5.0833, 19.0145)
  point P2 (-11.4211, -2.2)
  point P25 (-11.4211, -2.2)
  point P7 (7.0123, 43.8)
  point P27 (7.0123, 43.8)
  point P22 (7.1686, 14.1022)
  point P23 (25.776, 60.5109)
  point P24 (-11.4388, -32.3065)
  point P28 (57.0123, 43.8)
  point P29 (34.8575, 32.6356)
  coincident L3 P21
  coincident P2 P25
  parallel L13 L17
  coincident P7 P27
  dimension "d88" distance P21 P22 = 13.2
  dimension "d89" distance P22 P23 = 50
  dimension "d90" distance P22 P24 = 50
  dimension "d91" distance P27 P28 = 50
  dimension "d92" distance P27 P29 = 30
extrude "Extrude10" new body sketch "Sketch10" profile of L1 L2 L3 L4 L5 L14 L15 L16 L17 L19 along normal blind 2
move "Move1"
sketch "Sketch11" plane through (0, 0, 2) normal (0, 0, 1) x axis (-1, 0, 0)
  line L1 (0.6323, -2.2) -> (-11.4211, -2.2)
  line L2 (17.4051, 39.633) -> (0.6323, -2.2)
  line L3 (7.0123, 43.8) -> (17.4051, 39.633)
  line L4 (3.9887, 36.2589) -> (7.0123, 43.8)
  line L5 (2.418, 37.7236) -> (3.9887, 36.2589)
  line L6 (-10.5895, 5.2816) -> (2.418, 37.7236)
  line L7 (-8.4377, 5.259) -> (-10.5895, 5.2816)
  line L8 (-11.4211, -2.2) -> (-8.4377, 5.259)
  line L9 (11.4644, 39.8602) -> (12.2087, 41.7165)
  line L10 (4.9672, 42.4652) -> (11.4644, 39.8602)
  line L11 (19.452, 36.6576) -> (10.1703, 40.379)
  line L12 (14.2412, 37.1163) -> (16.0976, 36.372)
  line L13 (14.8112, 38.5183) -> (14.2412, 37.1163)
  line L14 (-4.3662, -9.2924) -> (14.2412, 37.1163)
  point P10 (12.2087, 41.7165)
  point P13 (10.1703, 40.379)
  point P15 (16.0976, 36.372)
  point P17 (14.8112, 38.5183)
  point P11 (11.4644, 39.8602)
  point P12 (4.9672, 42.4652)
  point P14 (19.452, 36.6576)
  point P16 (14.2412, 37.1163)
  point P18 (-4.3662, -9.2924)
  midpoint L3 P10
  coincident L10 P13
  coincident L2 P15
  midpoint L11 P17
  dimension "d95" distance P10 P11 = 2
  dimension "d96" distance P11 P12 = 7
  dimension "d97" distance P13 P14 = 10
  dimension "d98" distance P15 P16 = 2
  dimension "d99" distance P16 P18 = 50
extrude "Extrude11" add sketch "Sketch11" profile of L2 L3 L4 L9 L10 L11 along normal blind 13
sketch "Sketch12" plane through (0, 0, 2) normal (0, 0, 1) x axis (-1, 0, 0)
  line L1 (6.268, 41.9437) -> (16.6608, 37.7767)
  line L2 (3.9887, 36.2589) -> (6.268, 41.9437)
  line L3 (2.418, 37.7236) -> (3.9887, 36.2589)
  line L4 (-10.5895, 5.2816) -> (2.418, 37.7236)
  line L5 (-8.4377, 5.259) -> (-10.5895, 5.2816)
  line L6 (-11.4211, -2.2) -> (-8.4377, 5.259)
  line L7 (0.6323, -2.2) -> (-11.4211, -2.2)
  line L8 (16.6608, 37.7767) -> (0.6323, -2.2)
  line L9 (14.8044, 38.521) -> (16.6608, 37.7767)
  line L10 (-0.0815, 1.3941) -> (14.8044, 38.521)
  line L11 (4, 1.3941) -> (-0.0815, 1.3941)
  point P2 (16.6608, 37.7767)
  point P10 (16.6608, 37.7767)
  point P11 (14.8044, 38.521)
  point P12 (-0.0815, 1.3941)
  point P13 (4, 1.3941)
  coincident P2 P10
  horizontal L11
  dimension "d102" distance P10 P11 = 2
  dimension "d103" distance P11 P12 = 40
  dimension "d104" distance P12 P13 = 4.0815
extrude "Extrude12" add of existing geometry blind 2
sketch "Sketch13" plane through (0, 0, 2) normal (0, 0, 1) x axis (-1, 0, 0)
  line L1 (6.268, 41.9437) -> (18.5171, 37.0324)
  line L2 (3.9887, 36.2589) -> (6.268, 41.9437)
  line L3 (2.418, 37.7236) -> (3.9887, 36.2589)
  line L4 (-10.5895, 5.2816) -> (2.418, 37.7236)
  line L5 (-8.4377, 5.259) -> (-10.5895, 5.2816)
  line L6 (-11.4211, -2.2) -> (-8.4377, 5.259)
  line L7 (0.6323, -2.2) -> (-11.4211, -2.2)
  line L8 (2.4886, -2.9443) -> (0.6323, -2.2)
  line L9 (18.5171, 37.0324) -> (2.4886, -2.9443)
  line L10 (16.6608, 37.7767) -> (18.5171, 37.0324)
  line L11 (1.7749, 0.6498) -> (16.6608, 37.7767)
  line L12 (7.7749, 0.6498) -> (1.7749, 0.6498)
  point P2 (18.5171, 37.0324)
  point P11 (18.5171, 37.0324)
  point P12 (16.6608, 37.7767)
  point P13 (1.7749, 0.6498)
  point P14 (7.7749, 0.6498)
  coincident P2 P11
  dimension "d107" distance P11 P12 = 2
  dimension "d108" distance P12 P13 = 40
  dimension "d109" distance P13 P14 = 6
extrude "Extrude13" add sketch "Sketch13" profile of L1 L9 L10 L11 L12 along normal blind 10
sketch "Sketch14" plane through (-3.161, 1.2674, 0) normal (-0.9282, 0.3721, 0) x axis (-0.3721, -0.9282, 0)
  line L1 (43.2636, 15) -> (43.2636, 0)
  line L2 (41.2636, 15) -> (43.2636, 15)
  line L3 (41.2636, 12) -> (41.2636, 15)
  line L4 (2.0655, 12) -> (41.2636, 12)
  line L5 (2.0655, 2) -> (2.0655, 12)
  line L6 (-1.8067, 2) -> (2.0655, 2)
  line L7 (-1.8067, 0) -> (-1.8067, 2)
  line L8 (43.2636, 0) -> (-1.8067, 0)
sketch "Sketch15" plane through (0, 0, 2) normal (0, 0, 1) x axis (-1, 0, 0)
  line L1 (1.7749, 0.6498) -> (3.9296, 0.6498)
  line L2 (16.6608, 37.7767) -> (1.7749, 0.6498)
  line L3 (6.268, 41.9437) -> (16.6608, 37.7767)
  line L4 (3.9887, 36.2589) -> (6.268, 41.9437)
  line L5 (2.418, 37.7236) -> (3.9887, 36.2589)
  line L6 (-10.5895, 5.2816) -> (2.418, 37.7236)
  line L7 (-8.4377, 5.259) -> (-10.5895, 5.2816)
  line L8 (-11.4211, -2.2) -> (-8.4377, 5.259)
  line L9 (0.6323, -2.2) -> (-11.4211, -2.2)
  line L10 (2.4886, -2.9443) -> (0.6323, -2.2)
  line L11 (3.9296, 0.6498) -> (2.4886, -2.9443)
  arc A1 centre (-11.4211, 40.5698) radius 42.7698 clockwise from (3.9296, 0.6498) to (-11.4211, -2.2)
  point P10 (-11.4211, -2.2)
  point P14 (-11.4211, -2.2)
  point P2 (3.9296, 0.6498)
  point P13 (3.9296, 0.6498)
  tangent L9 A1
  coincident P10 P14
  coincident P2 P13
extrude "Extrude14" cut sketch "Sketch15" profile of L9 L10 L11 A1 against normal blind 4
extrude "Extrude15" add of existing geometry blind 0.5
